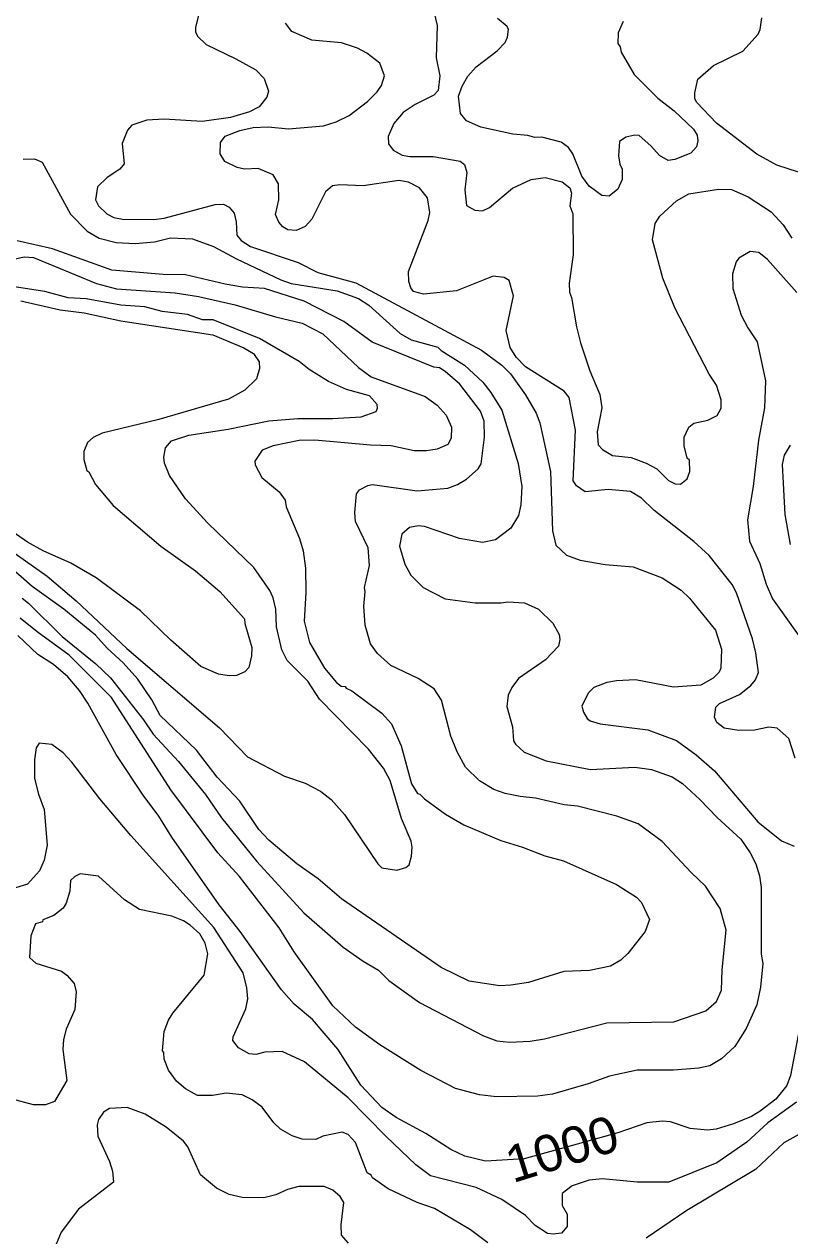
# Model space of a CAD drawing. Extents: x 447.8 to 473.9, y 7733.1 to 7760.8.
# Drawn here: x 469.73 to 471.4, y 7736.498 to 7739.144 of the extents above; entities that cross this region are included whole.
import ezdxf
from ezdxf.enums import TextEntityAlignment as Align

# ---------------------------------------------------------------- set-up
doc = ezdxf.new("R2010")
doc.units = 0
doc.header["$LTSCALE"] = 0.032
doc.layers.add('1', color=7, linetype='Continuous', lineweight=25)
doc.layers.add('2', color=7, linetype='Continuous', lineweight=13)
doc.layers.add('61', color=7, linetype='Continuous')

msp = doc.modelspace()

# ---------------------------------------------------------------- linework, layer by layer
at = {"layer": '1'}
for points in [[(470.1108, 7739.1657), (470.1035, 7739.1373), (470.1035, 7739.1268), (470.1077, 7739.1175), (470.1265, 7739.0997), (470.1918, 7739.0683), (470.2352, 7739.044), (470.2532, 7739.025), (470.2628, 7738.9976), (470.2593, 7738.9846), (470.2426, 7738.9632), (470.2217, 7738.9528), (470.1801, 7738.94), (470.1182, 7738.9313), (470.0349, 7738.9368), (469.9971, 7738.934), (469.965, 7738.9233), (469.9551, 7738.9127), (469.9433, 7738.8834), (469.9478, 7738.8391), (469.9383, 7738.8271), (469.911, 7738.8094), (469.89, 7738.7887), (469.8855, 7738.76), (469.8921, 7738.7475), (469.91, 7738.7295), (469.9251, 7738.722), (469.9444, 7738.7181), (470.0124, 7738.7173), (470.0349, 7738.7205), (470.1467, 7738.7501), (470.1648, 7738.7506), (470.1772, 7738.7443), (470.1877, 7738.7312), (470.1924, 7738.7124), (470.1935, 7738.6833), (470.203, 7738.6713), (470.2234, 7738.6581), (470.3279, 7738.6234), (470.3703, 7738.6016), (470.4532, 7738.5792), (470.7278, 7738.4321), (470.7722, 7738.3996), (470.791, 7738.3806), (470.8237, 7738.3349), (470.8469, 7738.2948), (470.8552, 7738.2735), (470.8779, 7738.1674), (470.8825, 7738.0379), (470.8901, 7738.006), (470.9132, 7737.9846), (470.9429, 7737.9737), (470.9973, 7737.9644), (471.0589, 7737.9589), (471.1222, 7737.9352), (471.1634, 7737.9082), (471.1815, 7737.8908), (471.2384, 7737.821), (471.2513, 7737.7794), (471.2497, 7737.7378), (471.246, 7737.7291), (471.2329, 7737.7159), (471.2061, 7737.7003), (471.1468, 7737.6961), (471.0637, 7737.712), (471.022, 7737.7104), (471.0009, 7737.7063), (470.9729, 7737.6955), (470.9607, 7737.6832), (470.9469, 7737.6546), (470.9501, 7737.6413)], [(469.7223, 7738.54), (469.8086, 7738.5203), (469.8605, 7738.5135), (469.9403, 7738.496), (470.1411, 7738.4655), (470.2092, 7738.4374), (470.2305, 7738.4249), (470.2427, 7738.4065), (470.2429, 7738.3918), (470.2368, 7738.3698), (470.211, 7738.3444), (470.1753, 7738.3252), (470.0237, 7738.2804), (469.8999, 7738.2507), (469.8805, 7738.2413), (469.8681, 7738.2303), (469.8599, 7738.211), (469.8598, 7738.1931), (469.8666, 7738.1691), (469.871, 7738.1664), (469.8855, 7738.1388), (469.9238, 7738.0928), (470.0277, 7738.0043), (470.1037, 7737.9499), (470.1566, 7737.905), (470.2104, 7737.8457), (470.2109, 7737.8356), (470.2268, 7737.7826), (470.226, 7737.7646), (470.22, 7737.7389), (470.211, 7737.7299), (470.1932, 7737.7217), (470.1769, 7737.7209), (470.1541, 7737.7249), (470.1153, 7737.7414), (470.0501, 7737.7989), (469.9838, 7737.863), (469.8865, 7737.9346), (469.8314, 7737.9671), (469.7713, 7737.9936), (469.7373, 7738.0127), (469.6422, 7738.0785)], [(471.402, 7738.0074), (471.3907, 7738.0731), (471.3844, 7738.1821), (471.3892, 7738.2026), (471.4019, 7738.2247)], [(471.3167, 7736.7588), (471.2778, 7736.7427), (471.2398, 7736.7309), (471.2212, 7736.7286), (471.1831, 7736.7324), (471.1399, 7736.747), (471.1216, 7736.7485), (471.0882, 7736.7446), (471.0255, 7736.7228), (470.923, 7736.6944), (470.8206, 7736.6661), (470.7364, 7736.6613), (470.6911, 7736.6719), (470.6607, 7736.6864), (470.6063, 7736.722), (470.5413, 7736.7569), (470.5104, 7736.7782), (470.4647, 7736.8273), (470.4144, 7736.9056), (470.3592, 7736.9704), (470.3188, 7737.0037), (470.2916, 7737.035), (470.201, 7737.1624), (470.1555, 7737.2209), (470.0517, 7737.3688), (470.0236, 7737.4145), (469.9895, 7737.4607), (469.9308, 7737.5489), (469.8689, 7737.6614), (469.8506, 7737.689), (469.8249, 7737.7188), (469.7934, 7737.7454), (469.7595, 7737.7675), (469.7157, 7737.8088)], [(470.9501, 7737.6413), (470.9584, 7737.6276), (470.9649, 7737.6224), (470.9865, 7737.6159), (471.0907, 7737.6031), (471.1532, 7737.5799)], [(471.1532, 7737.5799), (471.1959, 7737.5488), (471.2358, 7737.5135), (471.3309, 7737.4024), (471.3823, 7737.3608), (471.4097, 7737.3491)], [(471.4276, 7736.9823), (471.402, 7736.848), (471.3941, 7736.8263), (471.3701, 7736.7969), (471.3359, 7736.7702), (471.3167, 7736.7588)]]:
    msp.add_lwpolyline(points, dxfattribs=at)
at = {"layer": '2'}
for points in [[(470.621, 7739.1842), (470.6309, 7739.141), (470.6284, 7739.0704), (470.6365, 7739.0314), (470.6334, 7738.9992), (470.6239, 7738.9892), (470.5831, 7738.9682), (470.5566, 7738.9507), (470.5362, 7738.9273), (470.5243, 7738.8987), (470.5251, 7738.8824), (470.5352, 7738.8686), (470.5549, 7738.8579), (470.5715, 7738.8548), (470.6225, 7738.8552), (470.6812, 7738.845), (470.6905, 7738.8375), (470.6958, 7738.8199), (470.6911, 7738.7824), (470.6951, 7738.748), (470.713, 7738.7377), (470.7297, 7738.7363), (470.745, 7738.7434)], [(471.2414, 7737.619), (471.2361, 7737.6307), (471.2387, 7737.6529), (471.2472, 7737.6603), (471.2909, 7737.68), (471.3151, 7737.6998), (471.3253, 7737.7122), (471.3322, 7737.7279), (471.3266, 7737.7713), (471.3191, 7737.8015), (471.2843, 7737.9025), (471.2744, 7737.9201), (471.2242, 7737.9836), (471.1907, 7738.014), (471.1041, 7738.0829), (471.077, 7738.109), (471.053, 7738.1232), (471.0044, 7738.1281), (470.9539, 7738.1226), (470.9347, 7738.1355), (470.9278, 7738.1466), (470.933, 7738.2575), (470.9187, 7738.3289), (470.9079, 7738.3424), (470.8239, 7738.3955), (470.803, 7738.4168), (470.7899, 7738.4381), (470.7816, 7738.4751), (470.7977, 7738.5508), (470.7877, 7738.5843), (470.7772, 7738.5907), (470.753, 7738.5938), (470.6734, 7738.5616), (470.6012, 7738.5546), (470.5792, 7738.5599), (470.5732, 7738.5682), (470.5693, 7738.5818), (470.5682, 7738.604), (470.6115, 7738.7153), (470.6148, 7738.733), (470.6099, 7738.7646), (470.5921, 7738.7862), (470.5687, 7738.7989), (470.5472, 7738.8022), (470.4696, 7738.7911), (470.4189, 7738.7933), (470.4024, 7738.7906), (470.3871, 7738.7779), (470.3571, 7738.7179), (470.3429, 7738.7019), (470.3233, 7738.6933), (470.3052, 7738.6945), (470.294, 7738.7015), (470.2851, 7738.7119), (470.2783, 7738.7285), (470.2854, 7738.7606), (470.2847, 7738.7956), (470.2733, 7738.8149), (470.2401, 7738.8285), (470.2105, 7738.8271), (470.1944, 7738.8307), (470.1675, 7738.8442), (470.1577, 7738.8607), (470.1578, 7738.8857), (470.1686, 7738.8993), (470.2001, 7738.9116), (470.2294, 7738.9183), (470.2618, 7738.92), (470.3063, 7738.9153), (470.3828, 7738.9217), (470.4109, 7738.9303), (470.4388, 7738.9442), (470.4789, 7738.9748), (470.5, 7738.996), (470.5094, 7739.01), (470.5163, 7739.0313), (470.5058, 7739.0586), (470.4771, 7739.0808), (470.4574, 7739.0917), (470.4221, 7739.1029), (470.3576, 7739.1087), (470.3138, 7739.1282), (470.2998, 7739.1463)], [(471.0366, 7739.15), (471.0259, 7739.1251), (471.0253, 7739.1019), (471.03, 7739.0944), (471.0323, 7739.0824), (471.0606, 7739.0341), (471.1123, 7738.9825), (471.1482, 7738.9543), (471.1902, 7738.9147), (471.1985, 7738.9017), (471.2, 7738.8888), (471.1971, 7738.8758), (471.1845, 7738.8623), (471.1496, 7738.8481), (471.1351, 7738.8464), (471.1163, 7738.8571), (471.0974, 7738.8783), (471.0717, 7738.9007), (471.0622, 7738.9016), (471.0429, 7738.8968), (471.0288, 7738.888), (471.0269, 7738.8561), (471.0299, 7738.8381), (471.0348, 7738.8275), (471.0348, 7738.8049), (471.0252, 7738.7833), (471.0066, 7738.7684), (470.9905, 7738.7699), (470.9625, 7738.7904), (470.9468, 7738.8119), (470.9268, 7738.8609), (470.9176, 7738.8745), (470.9012, 7738.8861), (470.8593, 7738.8968), (470.8444, 7738.8961), (470.8287, 7738.9007), (470.7962, 7738.9037), (470.7259, 7738.9188), (470.6951, 7738.9328), (470.6822, 7738.9485), (470.6774, 7738.9865), (470.6852, 7739.0085), (470.6976, 7739.0301), (470.7161, 7739.051), (470.7618, 7739.0855), (470.7791, 7739.1036), (470.7846, 7739.1153), (470.7864, 7739.1324), (470.784, 7739.1388), (470.7626, 7739.1563)], [(471.4418, 7738.8135), (471.3724, 7738.8359), (471.3282, 7738.8597), (471.2404, 7738.9278), (471.1976, 7738.9728), (471.1933, 7738.9806), (471.1929, 7738.9939), (471.2001, 7739.024), (471.2342, 7739.0535), (471.2976, 7739.085), (471.3317, 7739.1223), (471.336, 7739.132), (471.3394, 7739.1578)], [(469.7274, 7738.8491), (469.7522, 7738.8495), (469.7693, 7738.8427), (469.8308, 7738.7287), (469.8672, 7738.692), (469.8931, 7738.6765), (469.9307, 7738.6669), (469.9717, 7738.6651), (470.0141, 7738.6689), (470.0489, 7738.6771), (470.0968, 7738.6754), (470.1432, 7738.6581), (470.1933, 7738.6313), (470.2901, 7738.5855), (470.3125, 7738.5776), (470.4125, 7738.5618), (470.4596, 7738.5448), (470.4821, 7738.5302), (470.5502, 7738.4688), (470.5745, 7738.4545), (470.6324, 7738.4387), (470.6395, 7738.4317), (470.6905, 7738.3996), (470.7303, 7738.362), (470.7484, 7738.3399), (470.7718, 7738.3007), (470.808, 7738.1847), (470.816, 7738.1341), (470.8136, 7738.0945), (470.8087, 7738.0707), (470.7918, 7738.0437), (470.7582, 7738.0178), (470.73, 7738.0119), (470.6799, 7738.0208), (470.6036, 7738.0471), (470.5905, 7738.0487), (470.5705, 7738.0446), (470.5535, 7738.0301), (470.5484, 7738.0039), (470.5605, 7737.965)], [(470.745, 7738.7434), (470.7955, 7738.7858), (470.8364, 7738.8047), (470.8666, 7738.8093), (470.9037, 7738.7997), (470.9206, 7738.7866)], [(470.9206, 7738.7866), (470.9241, 7738.7749), (470.9203, 7738.7474), (470.9273, 7738.7298), (470.9274, 7738.64), (470.919, 7738.5782), (470.9198, 7738.5589), (470.9242, 7738.5473), (470.9348, 7738.4828), (470.9435, 7738.4483), (470.9642, 7738.3873), (470.9861, 7738.3353), (470.99, 7738.3062), (470.9799, 7738.2535), (470.982, 7738.2254), (470.9918, 7738.2149), (471.0137, 7738.202), (471.0541, 7738.1978), (471.0872, 7738.1853), (471.11, 7738.1731), (471.1356, 7738.1474), (471.1506, 7738.1401), (471.1618, 7738.1394), (471.1762, 7738.1509), (471.1823, 7738.167), (471.1815, 7738.1919), (471.1768, 7738.1966), (471.1696, 7738.2235), (471.1703, 7738.2424), (471.1802, 7738.2637), (471.1912, 7738.2726), (471.2219, 7738.2791), (471.2416, 7738.2892), (471.2505, 7738.3057), (471.2505, 7738.3234), (471.2405, 7738.3559), (471.2246, 7738.3795), (471.1497, 7738.5246), (471.1237, 7738.5892), (471.1007, 7738.6728), (471.1068, 7738.7086), (471.1169, 7738.7247), (471.153, 7738.7583), (471.1802, 7738.7734), (471.2452, 7738.7838), (471.2734, 7738.783), (471.3093, 7738.7668), (471.3597, 7738.7341), (471.3861, 7738.7058), (471.4046, 7738.6769)], [(470.2374, 7737.3153), (470.3401, 7737.2036), (470.426, 7737.1282), (470.4693, 7737.098), (470.5032, 7737.0782), (470.5257, 7737.0558), (470.5927, 7737.008), (470.7319, 7736.9346), (470.7611, 7736.9241), (470.7885, 7736.921), (470.8336, 7736.9234), (470.8654, 7736.9287), (471.0009, 7736.9633), (471.1476, 7736.9658), (471.217, 7736.9897), (471.2406, 7737.0096), (471.2513, 7737.0343), (471.253, 7737.0791), (471.2617, 7737.1653), (471.2484, 7737.2128), (471.2166, 7737.2618), (471.1854, 7737.2913), (471.122, 7737.3595), (471.0693, 7737.3978), (471.023, 7737.4148), (470.9371, 7737.4363), (470.9079, 7737.4396), (470.8454, 7737.454), (470.8117, 7737.4572), (470.779, 7737.4642), (470.7547, 7737.473), (470.7233, 7737.4915), (470.6925, 7737.5215), (470.6743, 7737.5547), (470.6611, 7737.5893), (470.6402, 7737.668), (470.6245, 7737.6926), (470.5892, 7737.7152), (470.53, 7737.7437), (470.5005, 7737.7695), (470.4851, 7737.7909), (470.4738, 7737.8318), (470.4706, 7737.8728), (470.4737, 7737.9044), (470.4722, 7737.9137), (470.4834, 7737.9622), (470.4801, 7738.0005), (470.453, 7738.058), (470.4514, 7738.0778), (470.4546, 7738.1182), (470.4616, 7738.1268), (470.4796, 7738.1366), (470.4898, 7738.1385), (470.5873, 7738.1249), (470.6544, 7738.1308), (470.6754, 7738.1384), (470.6953, 7738.1507), (470.7204, 7738.1727), (470.727, 7738.1838), (470.7343, 7738.242), (470.7335, 7738.2769), (470.7254, 7738.2988), (470.6805, 7738.3581), (470.6487, 7738.3857), (470.6358, 7738.3933), (470.6238, 7738.3953), (470.4893, 7738.4498), (470.4273, 7738.4944), (470.341, 7738.5391), (470.2544, 7738.5665), (470.206, 7738.5697), (470.1686, 7738.5759), (470.0817, 7738.5969), (470.0331, 7738.5974), (469.9209, 7738.6066), (469.7913, 7738.6535), (469.7145, 7738.6706)], [(471.4155, 7738.5581), (471.352, 7738.63), (471.3326, 7738.6451), (471.3141, 7738.6475), (471.2889, 7738.6327), (471.2835, 7738.6253), (471.2754, 7738.5986), (471.2763, 7738.5664), (471.294, 7738.5085), (471.3087, 7738.4806), (471.3293, 7738.4504), (471.3475, 7738.3649), (471.3451, 7738.3065), (471.3323, 7738.2355), (471.3203, 7738.1341), (471.3083, 7738.0619), (471.3123, 7738.0151), (471.3349, 7737.9662), (471.3491, 7737.921), (471.3627, 7737.8888), (471.444, 7737.7751)], [(469.6849, 7738.626), (469.7299, 7738.6362), (469.7501, 7738.6347), (469.8879, 7738.5777), (469.9309, 7738.5659), (470.0592, 7738.5569), (470.1102, 7738.5489), (470.19, 7738.5312), (470.278, 7738.5045), (470.3362, 7738.4911), (470.3811, 7738.4677), (470.4591, 7738.3945), (470.4868, 7738.3738), (470.6046, 7738.3312), (470.6312, 7738.3122), (470.6505, 7738.2899), (470.6621, 7738.2636), (470.6614, 7738.2402), (470.654, 7738.226), (470.631, 7738.2157), (470.6075, 7738.2123), (470.5809, 7738.2123), (470.5303, 7738.2234), (470.4858, 7738.2245), (470.3643, 7738.2354), (470.3295, 7738.2346), (470.2734, 7738.2234), (470.2488, 7738.2136), (470.2334, 7738.1895), (470.2335, 7738.1816), (470.2484, 7738.1538), (470.2862, 7738.1224), (470.2989, 7738.1047), (470.3013, 7738.0899), (470.3308, 7738.021), (470.3384, 7737.9939), (470.3439, 7737.9564), (470.3447, 7737.9032), (470.3408, 7737.84), (470.3526, 7737.7941), (470.3848, 7737.7377), (470.4111, 7737.7065), (470.4217, 7737.6986), (470.4303, 7737.6975), (470.4321, 7737.694), (470.4449, 7737.688), (470.5104, 7737.6393), (470.5313, 7737.6161), (470.5521, 7737.5684), (470.5747, 7737.4853), (470.5878, 7737.4638)], [(470.5629, 7737.3027), (470.5696, 7737.3086), (470.5747, 7737.327), (470.5764, 7737.3471), (470.5741, 7737.3602), (470.5528, 7737.4094), (470.5281, 7737.4927), (470.5135, 7737.5196), (470.481, 7737.5607), (470.3742, 7737.6701), (470.3485, 7737.7091), (470.3035, 7737.7547), (470.2917, 7737.778), (470.2806, 7737.8281), (470.279, 7737.8663), (470.2734, 7737.8913), (470.266, 7737.9072), (470.2307, 7737.9576), (470.1302, 7738.0541), (470.0816, 7738.1074), (470.0469, 7738.1587), (470.0361, 7738.1854), (470.0346, 7738.1985), (470.0381, 7738.219), (470.0509, 7738.2338), (470.089, 7738.2467), (470.1747, 7738.2596), (470.2634, 7738.2779), (470.3267, 7738.2827), (470.4023, 7738.2828), (470.4654, 7738.2867), (470.4979, 7738.2984), (470.501, 7738.3052), (470.5001, 7738.3135), (470.4835, 7738.3322), (470.4334, 7738.3463), (470.3941, 7738.3635), (470.3517, 7738.3895), (470.33, 7738.4072), (470.2432, 7738.4574), (470.1419, 7738.4984), (470.1191, 7738.4985), (470.0858, 7738.5096), (470.0309, 7738.5166), (469.9928, 7738.5264), (469.9403, 7738.5306), (469.8652, 7738.5441), (469.8258, 7738.5466), (469.7748, 7738.5601), (469.6847, 7738.5737)], [(469.7028, 7737.9931), (469.7799, 7737.9387), (469.8432, 7737.885), (469.9536, 7737.7807), (470.1558, 7737.6076), (470.2167, 7737.5444), (470.2977, 7737.5019), (470.3426, 7737.4867), (470.376, 7737.4691), (470.3994, 7737.4507), (470.4287, 7737.4181), (470.5013, 7737.3105), (470.5102, 7737.3016), (470.543, 7737.2968), (470.5629, 7737.3027)], [(470.7696, 7737.3617), (470.8171, 7737.3472), (470.8662, 7737.328), (470.9069, 7737.3167), (471.0223, 7737.2654), (471.0659, 7737.2375), (471.0765, 7737.2264), (471.0941, 7737.1889), (471.0846, 7737.1624), (471.0473, 7737.1144), (471.0314, 7737.1001), (471.0092, 7737.0869), (470.9632, 7737.0779), (470.9075, 7737.0755), (470.83, 7737.0516), (470.7916, 7737.0452), (470.7674, 7737.0444), (470.7011, 7737.0541), (470.6394, 7737.0838), (470.4219, 7737.234), (470.3714, 7737.2774), (470.3247, 7737.3106), (470.2635, 7737.362), (470.2419, 7737.3853), (470.2002, 7737.447), (470.151, 7737.4994), (470.1056, 7737.5584), (470.0268, 7737.6341), (470.0082, 7737.6685), (469.9774, 7737.7139), (469.9461, 7737.7492), (469.911, 7737.7811), (469.8852, 7737.81), (469.8162, 7737.8669), (469.7473, 7737.9157), (469.6933, 7737.9635)], [(470.5605, 7737.965), (470.5733, 7737.9408), (470.6007, 7737.9141), (470.6482, 7737.8891), (470.7139, 7737.8804), (470.7709, 7737.8803)], [(470.7709, 7737.8803), (470.7848, 7737.8827), (470.8216, 7737.8805), (470.8518, 7737.8668), (470.8831, 7737.8358), (470.897, 7737.8114), (470.8985, 7737.8003), (470.8954, 7737.7861), (470.8676, 7737.7562), (470.8086, 7737.7149), (470.7936, 7737.6954), (470.7861, 7737.6788), (470.7833, 7737.654), (470.7952, 7737.6094), (470.7977, 7737.5794), (470.8019, 7737.5715), (470.8209, 7737.5542), (470.8688, 7737.5356), (470.9656, 7737.5165), (471.0625, 7737.5212), (471.0987, 7737.5165), (471.1436, 7737.5006), (471.1666, 7737.4858), (471.2043, 7737.4513), (471.2418, 7737.4113), (471.2936, 7737.3644), (471.3142, 7737.3347), (471.3263, 7737.3103), (471.3346, 7737.284), (471.3378, 7737.259), (471.3379, 7737.1133), (471.3419, 7737.0928), (471.3364, 7737.0415), (471.3283, 7737.0025), (471.305, 7736.9506), (471.2807, 7736.9118), (471.2516, 7736.885), (471.2259, 7736.8697), (471.2019, 7736.8641), (471.1469, 7736.8603), (471.0675, 7736.86), (471.0071, 7736.8467), (470.9605, 7736.8301), (470.8823, 7736.8078), (470.8496, 7736.8031), (470.7604, 7736.8016), (470.7235, 7736.8063), (470.6713, 7736.8197), (470.5953, 7736.8593), (470.5056, 7736.9154), (470.4524, 7736.9535), (470.403, 7737.0005), (470.3192, 7737.1185), (470.286, 7737.1704), (470.1994, 7737.2827), (470.1521, 7737.3348), (470.0495, 7737.4718), (469.9204, 7737.6738), (469.828, 7737.7663), (469.7582, 7737.8168), (469.7213, 7737.8472)], [(469.7253, 7737.8902), (469.7394, 7737.8795), (469.8127, 7737.8072), (469.886, 7737.7475), (469.9184, 7737.7166), (469.9898, 7737.6252)], [(469.9898, 7737.6252), (470.0113, 7737.5936), (470.0667, 7737.5339), (470.1253, 7737.4617), (470.1601, 7737.4109), (470.2374, 7737.3153)], [(471.3731, 7737.6066), (471.3547, 7737.6086), (471.3231, 7737.6022), (471.2891, 7737.6016), (471.2573, 7737.607), (471.2414, 7737.619)], [(471.4125, 7737.5415), (471.3986, 7737.5845), (471.3731, 7737.6066)], [(471.4154, 7736.79), (471.3526, 7736.7453), (471.3064, 7736.7027), (471.2412, 7736.6573), (471.1362, 7736.6155), (471.0674, 7736.6155), (470.9916, 7736.6227), (470.9624, 7736.6195), (470.9258, 7736.6073), (470.9038, 7736.5909), (470.9035, 7736.5646), (470.9148, 7736.5453), (470.9145, 7736.5187), (470.9019, 7736.5041), (470.8838, 7736.5017), (470.8717, 7736.5033), (470.8447, 7736.5206), (470.824, 7736.5425), (470.7724, 7736.5772), (470.7163, 7736.6038), (470.6162, 7736.6293), (470.5842, 7736.6534), (470.5193, 7736.715), (470.4364, 7736.7996), (470.3415, 7736.8784), (470.2926, 7736.9008), (470.2548, 7736.8993), (470.2352, 7736.8945), (470.2208, 7736.8953), (470.1976, 7736.9085), (470.1853, 7736.9248), (470.1855, 7736.9329), (470.2132, 7736.9938), (470.2179, 7737.0155), (470.2155, 7737.0394), (470.2076, 7737.0724), (470.1435, 7737.1718), (469.9623, 7737.3723), (469.8948, 7737.4526), (469.8335, 7737.5323), (469.8148, 7737.5525), (469.7903, 7737.5711), (469.7627, 7737.5738), (469.7562, 7737.5639), (469.7524, 7737.5376), (469.7524, 7737.4969), (469.7607, 7737.4624), (469.7735, 7737.4288), (469.7796, 7737.3513), (469.7734, 7737.3183), (469.7635, 7737.2953), (469.7372, 7737.266), (469.6918, 7737.252)], [(470.5878, 7737.4638), (470.5932, 7737.4626), (470.6034, 7737.4523), (470.649, 7737.4188), (470.6889, 7737.3953), (470.7696, 7737.3617)], [(470.4527, 7736.7019), (470.4369, 7736.7196), (470.4237, 7736.7245), (470.3813, 7736.7158), (470.3663, 7736.7085), (470.3364, 7736.7096), (470.3147, 7736.7166), (470.2893, 7736.7308), (470.2744, 7736.7451), (470.2491, 7736.7792), (470.2269, 7736.795), (470.2053, 7736.8058), (470.1704, 7736.8095), (470.1408, 7736.8045), (470.1078, 7736.8046), (470.082, 7736.8192), (470.062, 7736.8358), (470.0447, 7736.8597), (470.0353, 7736.8836), (470.0345, 7736.8982), (470.0314, 7736.9019), (470.0354, 7736.9445), (470.0446, 7736.9692), (470.0541, 7736.9844), (470.1225, 7737.0676), (470.1307, 7737.1137), (470.1247, 7737.1372), (470.113, 7737.1574), (470.0917, 7737.1766), (470.0772, 7737.1858), (470.0518, 7737.1959), (469.9812, 7737.2111), (469.9484, 7737.232), (469.8918, 7737.2832), (469.8518, 7737.2886), (469.8403, 7737.283), (469.8311, 7737.2744), (469.829, 7737.2508), (469.8212, 7737.2245), (469.8151, 7737.2138), (469.7943, 7737.1976), (469.7705, 7737.1881), (469.7697, 7737.1838), (469.7542, 7737.1797), (469.7442, 7737.153), (469.7417, 7737.1062), (469.755, 7737.0935), (469.8111, 7737.0758), (469.8227, 7737.0676), (469.8387, 7737.0492), (469.8429, 7737.0307), (469.8405, 7736.9922), (469.8213, 7736.9496), (469.8155, 7736.927), (469.8141, 7736.9053), (469.8229, 7736.8371), (469.7956, 7736.7912), (469.7764, 7736.7839), (469.7504, 7736.7839), (469.652, 7736.8108)], [(470.4375, 7736.4819), (470.4225, 7736.4995), (470.4212, 7736.5223), (470.4272, 7736.5711), (470.4191, 7736.5842), (470.4032, 7736.5978), (470.3843, 7736.6058), (470.3288, 7736.6057), (470.3045, 7736.5996), (470.2789, 7736.5877), (470.2525, 7736.581), (470.2053, 7736.5819), (470.1773, 7736.5888), (470.1493, 7736.6023), (470.1148, 7736.6316), (470.0872, 7736.6927), (470.0776, 7736.7046), (470.0396, 7736.7355), (469.9936, 7736.7642), (469.9546, 7736.7782), (469.9158, 7736.7766), (469.9029, 7736.7683), (469.8922, 7736.7524), (469.8887, 7736.7408), (469.8905, 7736.7155), (469.9162, 7736.6608), (469.9223, 7736.6395), (469.9246, 7736.6151), (469.8484, 7736.5568), (469.8101, 7736.5064), (469.792, 7736.4628)], [(471.4531, 7736.738), (471.3876, 7736.701), (471.3253, 7736.6429), (471.1755, 7736.5537), (471.087, 7736.4928)], [(470.5873, 7736.5708), (470.5237, 7736.6009), (470.4897, 7736.6247), (470.4866, 7736.6306), (470.4785, 7736.6359), (470.4527, 7736.7019)], [(470.7413, 7736.4827), (470.7037, 7736.5116), (470.6254, 7736.558), (470.5873, 7736.5708)]]:
    msp.add_lwpolyline(points, dxfattribs=at)

# ---------------------------------------------------------------- texts
at = {"layer": '61', "width": 1.05}
msp.add_text('1000', height=0.08, rotation=17.314, dxfattribs=at).set_placement((470.9151, 7736.6501), align=Align.CENTER)

doc.saveas('drawing.dxf')
